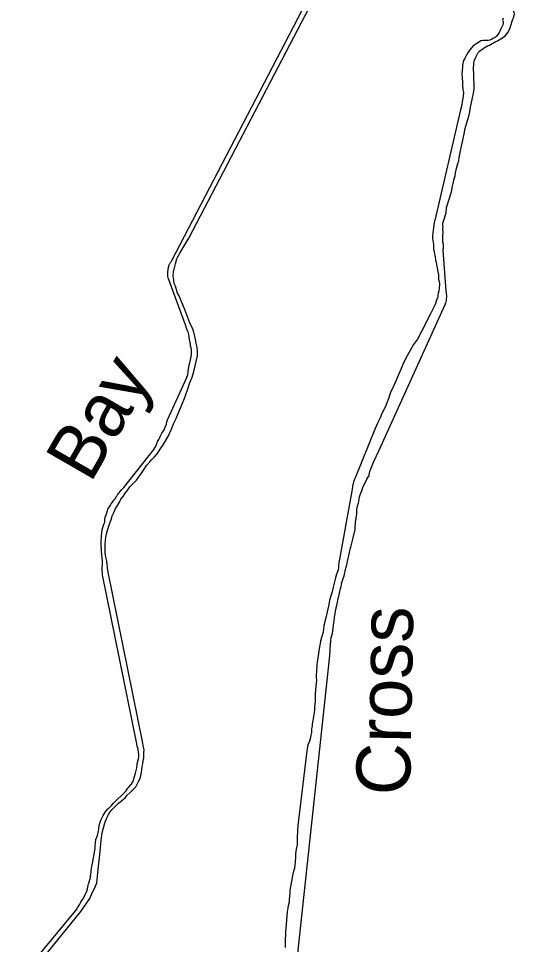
# Model space of a CAD drawing. Extents: x 1720274 to 1751788, y 372074 to 391887.
# Drawn here: x 1722285 to 1723051, y 386894 to 388322 of the extents above; entities that cross this region are included whole.
import ezdxf

# ---------------------------------------------------------------- set-up
doc = ezdxf.new("R2010")
doc.units = 0
doc.layers.add('Level 9', color=7, linetype='Continuous')

msp = doc.modelspace()

# ---------------------------------------------------------------- linework, layer by layer
at = {"layer": 'Level 9'}
for points in [[(1722422.5, 387563.3), (1722423.2, 387565.1), (1722424.2, 387567), (1722425.4, 387568.9), (1722426.9, 387571.3), (1722428.3, 387573.4), (1722430.2, 387576.2), (1722432.2, 387579), (1722434.1, 387581.3), (1722435.5, 387583.8), (1722436.7, 387585.3), (1722437.9, 387587.4), (1722439.1, 387589.1), (1722439.8, 387590), (1722442.7, 387593), (1722444.7, 387595.5), (1722445.9, 387597), (1722447.6, 387599), (1722494.3, 387657.9), (1722494.6, 387658.5), (1722496.8, 387661.6), (1722498.1, 387665), (1722499.1, 387667.5), (1722499.9, 387669.9), (1722501.6, 387672.7), (1722503.1, 387675.7), (1722503.9, 387677.5), (1722505.5, 387680.5), (1722506.5, 387682.6), (1722510.2, 387687.5), (1722511.6, 387692), (1722513.4, 387696.7), (1722514.2, 387699.9), (1722514.9, 387703.2), (1722545, 387768.4), (1722545.2, 387769.6), (1722545.8, 387770.9), (1722546.5, 387772.8), (1722546.8, 387776.1), (1722547.1, 387779.2), (1722547.8, 387784), (1722548.7, 387788.1), (1722549.5, 387790.9), (1722550.7, 387795.8), (1722551, 387798.4), (1722551.7, 387800.8), (1722552, 387803.5), (1722552.2, 387806.1), (1722552.3, 387809.6), (1722552.1, 387811.5), (1722551.5, 387814.4), (1722550.7, 387816.9), (1722550.5, 387819.9), (1722550.1, 387822.6), (1722549.6, 387825.1), (1722549.1, 387827.2), (1722548.6, 387829.5), (1722548.3, 387832.2), (1722547.8, 387834.2), (1722547.3, 387837.5), (1722546.4, 387839.4), (1722546, 387840.3), (1722545.6, 387841.6), (1722545.3, 387842.7), (1722544.6, 387843.9), (1722543.8, 387846.6), (1722543.3, 387848), (1722516.1, 387922.4), (1722515.8, 387924.1), (1722515.7, 387925.5), (1722515.7, 387926.9), (1722515.6, 387929), (1722515.6, 387930.9), (1722515.7, 387932.3), (1722516, 387933.8), (1722516.3, 387935.8), (1722516.7, 387938.4), (1722517.1, 387939.5), (1722517.3, 387941), (1722518.3, 387943.1), (1722518.6, 387944.2), (1722519, 387945), (1722519.6, 387946), (1722520.3, 387946.8), (1722521.2, 387948.1), (1722521.7, 387948.8), (1722781.8, 388448.1)], [(1722429.7, 387555.3), (1722432.2, 387560.2), (1722434.7, 387566.6), (1722438.1, 387571.1), (1722441, 387576.3), (1722443.3, 387580.9), (1722446.4, 387584.7), (1722449.4, 387588.8), (1722451.9, 387592.4), (1722453.9, 387595.4), (1722457, 387599.6), (1722461.1, 387604), (1722467.2, 387610.3), (1722475.9, 387622.5), (1722479.9, 387628.7), (1722482.8, 387632.7), (1722487.6, 387638.2), (1722490.6, 387641.3), (1722495, 387646), (1722498.1, 387649.5), (1722500.2, 387652.4), (1722506, 387661.1), (1722507.7, 387663.5), (1722516.4, 387678.6), (1722521.4, 387688.7), (1722524.6, 387696.8), (1722528, 387704.3), (1722530.4, 387710.1), (1722534.6, 387720), (1722540.8, 387734.8), (1722543.6, 387742), (1722545.8, 387749.4), (1722549.1, 387759.4), (1722553, 387769), (1722556, 387777.9), (1722561.6, 387802), (1722561.2, 387810.2), (1722561, 387814), (1722560.2, 387817.4), (1722559.3, 387821.3), (1722558.4, 387827.2), (1722556.9, 387834.1), (1722555.6, 387838.3), (1722554.4, 387843), (1722552.5, 387846.5), (1722550, 387851.3), (1722542.5, 387871.7), (1722532.5, 387895.3), (1722530.7, 387898.7), (1722528.5, 387905.5), (1722527.2, 387909.4), (1722525.5, 387913.6), (1722524.8, 387918.4), (1722524.3, 387921.5), (1722524, 387925.6), (1722524.4, 387932), (1722525.2, 387935.7), (1722526.4, 387939.8), (1722527.4, 387944), (1722529.6, 387951.3), (1722531.3, 387954.4), (1722533, 387958.4), (1722534.2, 387960.5), (1722548.2, 387983.5), (1722788.5, 388443.6)], [(1723047.8, 388319.7), (1723048.7, 388321.7), (1723049.6, 388324.9), (1723050.8, 388329.4), (1723050.1, 388331.7), (1723049.1, 388334.2), (1723047.8, 388338), (1723047.3, 388339.7), (1723046.9, 388341.4), (1723046.5, 388343), (1723045.6, 388344.5), (1723044.5, 388347.3), (1723043.3, 388349.6), (1723041.9, 388351.3), (1723040.4, 388353.1), (1723039.6, 388354), (1723030.7, 388364.7), (1723030, 388365.6)], [(1722814.2, 387591.6), (1722815.4, 387595.3), (1722816.7, 387598.6), (1722818.4, 387602.2), (1722820.1, 387606.1), (1722822.9, 387611.4), (1722824.5, 387614.2), (1722826.3, 387616.7), (1722826.7, 387618.9), (1722827.6, 387623.2), (1722828.8, 387627.6), (1722833.1, 387638), (1722842.1, 387656.3), (1722943.8, 387880.9), (1722944.9, 387884.1), (1722945.3, 387885.4), (1722945.6, 387887.3), (1722945.8, 387888.6), (1722946, 387890.2), (1722946.4, 387892.2), (1722946.5, 387893.8), (1722946.1, 387895.1), (1722946, 387897.9), (1722945.8, 387898.7), (1722945.7, 387900), (1722945.4, 387901.9), (1722940.8, 387965.1), (1722940.9, 387966), (1722941.4, 387968.7), (1722941.4, 387972.2), (1722941.3, 387973.8), (1722940.2, 387977.2), (1722940, 387980.7), (1722940, 387985.9), (1722940.6, 387993.9), (1722940.4, 387997.2), (1722940.6, 387999.9), (1722940.4, 388003.3), (1722940.4, 388006.4), (1722941.4, 388009.6), (1722945.1, 388022.7), (1722945.5, 388024.9), (1722945.7, 388027.5), (1722946, 388030.7), (1722953.3, 388055.1), (1722955, 388063.8), (1722956.1, 388067.8), (1722957.1, 388073.1), (1722958.3, 388076.3), (1722959.1, 388079.7), (1722959.7, 388084.3), (1722961.6, 388092.7), (1722963.5, 388098.5), (1722964.7, 388102.7), (1722965.3, 388107.6), (1722967.6, 388118.2), (1722968.8, 388125.4), (1722969.8, 388130.2), (1722970.8, 388134.7), (1722972.7, 388141.9), (1722973.5, 388146.6), (1722974.3, 388151.2), (1722979.9, 388169.9), (1722981, 388173.9), (1722981.7, 388178.2), (1722982.3, 388181.9), (1722982.8, 388185.4), (1722986.9, 388204.5), (1722987.6, 388207.7), (1722988.5, 388213.4), (1722988.8, 388216.5), (1722987.8, 388234.7), (1722987.9, 388236.4), (1722987.8, 388238.6), (1722987.7, 388243.1), (1722987.5, 388245.3), (1722987.8, 388251.9), (1722988, 388254), (1722989.2, 388258.2), (1722991.3, 388262.7), (1722992.8, 388265.5), (1722993.6, 388267.6), (1722994.9, 388269.9), (1722997, 388272.1), (1722998.7, 388273.3), (1723001.9, 388275.7), (1723004.5, 388277.7), (1723006.6, 388278.6), (1723009.1, 388280), (1723012, 388281.3), (1723016.3, 388283.7), (1723018.5, 388284.9), (1723020.9, 388286.3), (1723024.5, 388287.9), (1723027.4, 388289.6), (1723031.1, 388291.7), (1723036.6, 388295.8), (1723040.9, 388301), (1723043.6, 388307), (1723045.4, 388311.7), (1723047.8, 388319.7)], [(1723033.3, 388322.9), (1723032.9, 388321.2), (1723032.5, 388319.9), (1723033.2, 388317.9), (1723033.5, 388315.7), (1723033.3, 388313.7), (1723031.9, 388310.5), (1723029.9, 388306.1), (1723028.3, 388302.9), (1723027.3, 388300.7), (1723025.5, 388298.1), (1723022.7, 388294.6), (1723021.7, 388293.6), (1723019.2, 388292.7), (1723017.2, 388291.2), (1723015.4, 388290.1), (1723013.8, 388289.4), (1723012.7, 388288.9), (1723010.4, 388288.3), (1723005, 388288.2), (1723002.2, 388288.4), (1722998.9, 388287.7), (1722996.7, 388286.3), (1722986.8, 388280.1), (1722984.3, 388277), (1722981.6, 388273.2), (1722979.2, 388270.2), (1722976.9, 388265.7), (1722973.9, 388260.7)], [(1722973.9, 388260.7), (1722972.1, 388257.3), (1722970.6, 388250.3), (1722970.4, 388247.4), (1722969.8, 388242.3), (1722969.5, 388235.5), (1722969.8, 388232.3), (1722970.1, 388229.5), (1722970.6, 388224.9), (1722970.6, 388220.3), (1722970.7, 388217.6), (1722971, 388214.9), (1722971.3, 388212.4), (1722971.6, 388210), (1722971.9, 388209.3), (1722972.2, 388207.8), (1722970.9, 388198.7), (1722970.2, 388194), (1722969.3, 388189.2), (1722967.6, 388181.6), (1722927.7, 388010.5), (1722927.4, 388009.9), (1722926.6, 388007.3), (1722926.3, 388004.7), (1722926.2, 388002.8), (1722925.9, 387999.5), (1722925.3, 387995.7), (1722924.9, 387991.5), (1722924.2, 387986.7), (1722924.2, 387982.9), (1722924.7, 387979.9), (1722925.5, 387976.8), (1722925.8, 387974.4), (1722925.9, 387969.1), (1722926, 387966.2), (1722926.6, 387961.9), (1722928.4, 387954.6), (1722929.1, 387949.4), (1722929.7, 387946.3), (1722930.6, 387942.3), (1722930.8, 387940.1), (1722931.3, 387937.5), (1722932.1, 387934), (1722932.6, 387931.3), (1722933.3, 387926.9), (1722933.6, 387922.7), (1722933.5, 387919.5), (1722934.3, 387916.4), (1722935.2, 387913.4), (1722935, 387911.2), (1722934.7, 387907.2), (1722934.7, 387905.3), (1722934.1, 387902.1), (1722933.1, 387898.4), (1722932.7, 387894.9), (1722932.3, 387892.5), (1722930.9, 387889.2), (1722929.8, 387886.2), (1722928.7, 387882.6), (1722927.8, 387879.9), (1722926.9, 387878.2), (1722921.3, 387866.9), (1722917.4, 387859.8), (1722914.4, 387853.2), (1722900.9, 387827.8), (1722895.1, 387819.4), (1722889.8, 387810.1), (1722883.3, 387798.3), (1722878.4, 387788.7), (1722874.9, 387779.6), (1722862.8, 387752.5), (1722860, 387746.7), (1722858.7, 387743.8), (1722855.7, 387734.7), (1722854.2, 387730.4), (1722852.2, 387725.5), (1722849.5, 387719.5), (1722846.1, 387712.7), (1722843.2, 387706.3), (1722839.8, 387699), (1722835.9, 387689.6), (1722805.1, 387614.5), (1722804.2, 387612.4), (1722802.4, 387607.5), (1722800.9, 387600.9), (1722800.3, 387596.3), (1722799.9, 387593), (1722779.4, 387482.3), (1722779, 387479.3), (1722779, 387475.3), (1722778.6, 387472), (1722777.3, 387468.8), (1722775.9, 387465), (1722774.3, 387459.2), (1722772.9, 387453.3), (1722771.1, 387445), (1722769.1, 387438), (1722767.2, 387431.5), (1722765.3, 387424.4), (1722763.6, 387415.9), (1722761.6, 387407.2)], [(1722715.7, 386875.1), (1722765.2, 387334.5), (1722765.9, 387339.9), (1722766, 387345.9), (1722766.4, 387350.4), (1722766.8, 387356.1), (1722767.1, 387362), (1722767.9, 387367.4), (1722770, 387373.7), (1722771.5, 387386.6), (1722772.2, 387392.5), (1722773, 387398.8), (1722774.1, 387404.1), (1722774.7, 387408.2), (1722775.6, 387412.7), (1722776.3, 387417.3), (1722777.5, 387422.1), (1722778.8, 387427.3), (1722779.6, 387430.8), (1722780.7, 387435.6), (1722782.4, 387443), (1722783.2, 387445.8), (1722783.7, 387448.9), (1722783.9, 387450.5), (1722786, 387456.8), (1722787.7, 387462.5), (1722789.3, 387469.5), (1722790.4, 387474.5), (1722792.2, 387479.5), (1722793.2, 387484.5), (1722794.5, 387491.5), (1722796.5, 387501.1), (1722797.3, 387504.3), (1722797.9, 387506.9), (1722799, 387510.6), (1722801, 387519), (1722804.8, 387533.8), (1722805.5, 387547), (1722806.2, 387550.3), (1722806.5, 387553), (1722806.7, 387554.3), (1722807.2, 387557.2), (1722807.4, 387559.9), (1722807.5, 387563.7), (1722807.9, 387568.2), (1722808.3, 387569.8), (1722809.8, 387574.9), (1722810.3, 387577.2), (1722811, 387580.1), (1722811.4, 387584.4), (1722812.3, 387587.4), (1722814.2, 387591.6)], [(1722285.1, 386839.2), (1722375.4, 386948.7), (1722375.8, 386950.1), (1722377, 386952.1), (1722378.6, 386954.4), (1722379.5, 386956.2), (1722381.4, 386959.1), (1722383, 386961.6), (1722384.7, 386964), (1722385.7, 386966.2), (1722387, 386968.8), (1722389, 386972.5), (1722390.4, 386976.1), (1722391.5, 386979.5), (1722392.8, 386985.1), (1722393.3, 386987.5), (1722393.8, 386988.6), (1722394.7, 386992), (1722395.2, 386994.2), (1722396, 386996.8), (1722396.3, 387000), (1722396.7, 387001.8), (1722397.1, 387006.1), (1722397.3, 387008.1), (1722398.8, 387017.2), (1722399.3, 387018.9), (1722403.4, 387041.9), (1722403.5, 387045.4), (1722403.9, 387050.7), (1722404.7, 387055.6), (1722406.8, 387061.9), (1722408.5, 387068.8), (1722409.2, 387072.6), (1722409.7, 387076.5), (1722410.4, 387081.1), (1722412.2, 387085.8), (1722414, 387089.9), (1722415.6, 387093), (1722418.7, 387097.9), (1722422.8, 387102.8), (1722424.1, 387103.7), (1722428.9, 387108.9), (1722431.9, 387111.9), (1722432.2, 387112.4), (1722433.1, 387113.2), (1722448.6, 387128.1), (1722450.8, 387130.3), (1722451.9, 387131.9), (1722453.8, 387134.7), (1722455.3, 387136.4), (1722459, 387140.7), (1722460.6, 387143.3), (1722462.6, 387146.9), (1722463.8, 387151.4), (1722465.5, 387158), (1722466.9, 387162.3), (1722467.7, 387166.2), (1722468.1, 387170.5), (1722468.4, 387172.4), (1722470.1, 387180.1), (1722470.6, 387183.5), (1722471, 387187.4), (1722470.5, 387190.9), (1722469.9, 387193.4), (1722469.6, 387195.6), (1722468.9, 387198.1), (1722468.5, 387199.5), (1722467.7, 387203.3), (1722467.2, 387206), (1722467.2, 387206.1), (1722414.8, 387463.8), (1722414.5, 387466.6), (1722414.3, 387470), (1722414.3, 387473.6), (1722414.6, 387480.6), (1722414.5, 387486), (1722414, 387489.8), (1722413.5, 387494.8), (1722413.1, 387500.7), (1722412.7, 387512.2), (1722412.7, 387513.5), (1722412.8, 387515.9), (1722413.1, 387521.9), (1722413.1, 387522.9), (1722413.3, 387524.9), (1722413.6, 387527.2), (1722413.8, 387529.2), (1722414.1, 387533.2), (1722415.5, 387537.3), (1722416.4, 387540.5), (1722417.4, 387543.1), (1722418.1, 387545.5), (1722418.3, 387549.6), (1722419.1, 387552.8), (1722420.3, 387556.5), (1722421.3, 387559.8), (1722422.5, 387563.3)], [(1722316.8, 386865.6), (1722381.5, 386944.4), (1722395, 386964.9), (1722398.9, 386973.7), (1722402.3, 386980), (1722403.8, 386983.7), (1722405.8, 386988.9), (1722408.2, 387009.6), (1722410.6, 387032.3), (1722412.8, 387054.8), (1722414.4, 387066.1), (1722418.1, 387081.5), (1722421.8, 387090.1), (1722423.9, 387094.3), (1722426.7, 387098.4), (1722429.2, 387101.4), (1722432.7, 387105.2), (1722434.6, 387107.4), (1722439.5, 387111.6), (1722444.5, 387115.7), (1722449.5, 387120.1), (1722452.9, 387123.9), (1722457.4, 387128.4), (1722462.2, 387133.1), (1722466, 387136.9), (1722470.3, 387145.1), (1722472.8, 387149.8), (1722474.8, 387159.3), (1722475.4, 387163.6), (1722476.2, 387168.5), (1722476.8, 387172.5), (1722477.7, 387177.2), (1722478.5, 387181.8), (1722478.7, 387185.8), (1722478.6, 387189.6), (1722478.9, 387194.2), (1722478.3, 387198.3), (1722476.9, 387204.2), (1722423.1, 387470.9), (1722421.2, 387484.9), (1722419.9, 387491.5), (1722419.1, 387498), (1722419, 387503.3), (1722418.8, 387509.7), (1722419.6, 387518), (1722420.9, 387527.5), (1722422.5, 387532.9), (1722426.6, 387545.3), (1722428.7, 387550.6), (1722429.7, 387555.3)], [(1722761.6, 387407.2), (1722759.8, 387399.7), (1722756.7, 387385.7), (1722755.3, 387375.8), (1722752.8, 387367.3), (1722751.3, 387361.5), (1722750.2, 387355.7), (1722749.2, 387350), (1722746.2, 387329), (1722745.9, 387326.5), (1722745.4, 387320.8), (1722745.1, 387318.7), (1722745, 387314.9), (1722744.7, 387309.8), (1722744.7, 387306.3), (1722744.9, 387301.2), (1722744.5, 387296.5), (1722744, 387291.8), (1722743.5, 387286.1), (1722743.1, 387280.8), (1722743, 387274.2), (1722743, 387268.2), (1722742.3, 387260.3), (1722742, 387255.6), (1722741.6, 387251.4), (1722740.7, 387245.4), (1722739.4, 387239.3), (1722738.6, 387233.5), (1722738.3, 387230.8), (1722737.5, 387226.2), (1722737.4, 387222.7), (1722737.2, 387220.6), (1722736.6, 387216.6), (1722735.9, 387212.9), (1722734.1, 387207.4), (1722732.4, 387202.9), (1722731.3, 387199.1), (1722730.8, 387195.2), (1722730.4, 387192.5), (1722716.2, 387077.3), (1722716, 387069.2), (1722715.3, 387058.1), (1722715.4, 387051.1), (1722715.4, 387047.3), (1722713.7, 387040.8), (1722712.9, 387033.8), (1722712.7, 387028.4), (1722712.3, 387021.1), (1722711.1, 387011.1), (1722709.6, 387007), (1722708.4, 387002), (1722707.7, 386997.6), (1722706.9, 386993.7), (1722706.1, 386989.1), (1722705.3, 386985.5), (1722704.4, 386980.6), (1722704.2, 386976.6), (1722703.9, 386972.3), (1722703.3, 386968.3), (1722703, 386963.1), (1722702.7, 386959.1), (1722701.5, 386953.6), (1722699.8, 386943.9), (1722698, 386918.6), (1722697.4, 386913.3), (1722697, 386897.1), (1722696.8, 386889)]]:
    msp.add_lwpolyline(points, dxfattribs=at)

# ---------------------------------------------------------------- texts
for s, rotation, p in [('Bay', 60, (1722396, 387603.9)), ('Cross', 89, (1722889.5, 387123.5))]:
    msp.add_text(s, height=83.42, rotation=rotation, dxfattribs=at).set_placement(p)

doc.saveas('drawing.dxf')
